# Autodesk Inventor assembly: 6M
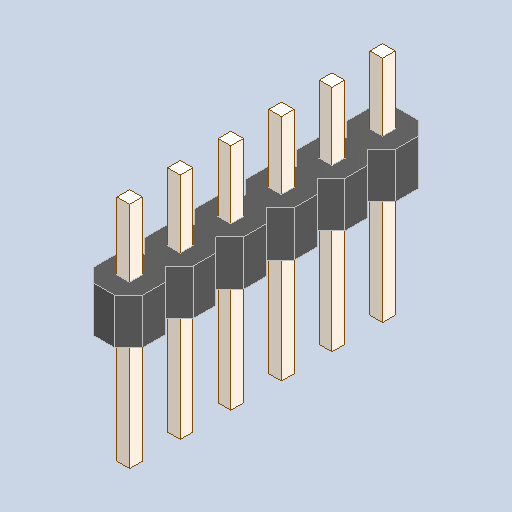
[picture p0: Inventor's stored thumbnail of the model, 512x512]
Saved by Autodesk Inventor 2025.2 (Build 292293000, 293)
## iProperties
Created: 2025-04
Part Number: 6M
Description: PART--DESC
Document SubType Name: Assembly
Designer: BennF
Author: BennF
Revision Number: NONE
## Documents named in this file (3)
- C:\Users\BennF\Nextcloud\Benutzer\CNC JarBeRi\existing parts\Electronics\RepRap A4988 Shied (USE WITHOUT ARDUINO)\reprap-a4988-1.snapshot.1\RepRap\RepRap\6M_1.iam
- C:\Users\BennF\Nextcloud\Benutzer\CNC JarBeRi\existing parts\Electronics\RepRap A4988 Shied (USE WITHOUT ARDUINO)\reprap-a4988-1.snapshot.1\RepRap\RepRap\6M Geometry.ipt
- C:\Users\BennF\Nextcloud\Benutzer\CNC JarBeRi\existing parts\Electronics\RepRap A4988 Shied (USE WITHOUT ARDUINO)\reprap-a4988-1.snapshot.1\RepRap\RepRap\pin18.ipt
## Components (2 placed, 2 different names)
1. 6M Geometry
2. pin18
